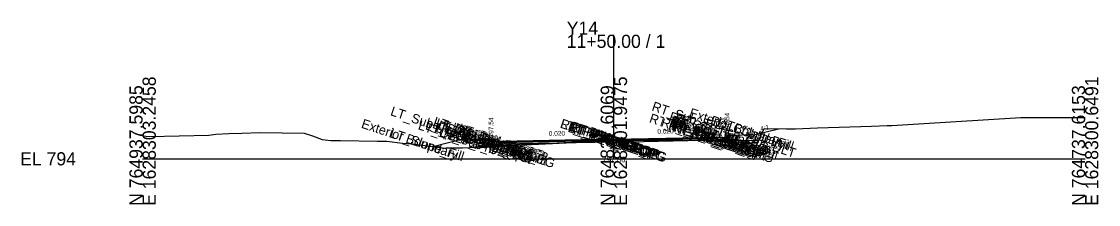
# Model space of a CAD drawing. Extents: x -26 to 1403, y -10 to 4517.
# Drawn here: x -25.7 to 202.8, y 2990.3 to 3029.1 of the extents above; entities that cross this region are included whole.
import ezdxf

# ---------------------------------------------------------------- set-up
doc = ezdxf.new("R2010")
doc.units = 0
for name, color, linetype in [('Default', 7, 'Continuous'), ('Exist CMT Pavement', 7, 'Continuous'), ('Exist Cross Section Cell', 7, 'Continuous'), ('Exist XS Center Line Elevation Label', 7, 'Continuous'), ('Exist XS Ground Line', 7, 'Continuous'), ('Prop CMT Conc Surface', 7, 'Continuous'), ('Prop CMT Concrete Structures', 7, 'Continuous'), ('Prop CMT Pvmt Course 1', 7, 'Continuous'), ('Prop CMT Pvmt Course 1 CG', 7, 'Continuous'), ('Prop CMT Pvmt Course 1 Wedge', 7, 'Continuous'), ('Prop CMT Pvmt Course 2', 7, 'Continuous'), ('Prop CMT Pvmt Course 2 Wedge', 7, 'Continuous'), ('Prop CMT Pvmt Course 3', 7, 'Continuous'), ('Prop CMT Pvmt Course 3 Wedge', 7, 'Continuous'), ('Prop CMT Pvmt Surface', 7, 'Continuous'), ('Prop CMT Pvmt Wedge Surface 1', 7, 'Continuous'), ('Prop CMT Pvmt Wedge Surface 2', 7, 'Continuous'), ('Prop CMT Pvmt Wedge Surface 3', 7, 'Continuous'), ('Prop CMT Slope Grass', 7, 'Continuous'), ('Prop CMT Subgrade Earthwork', 7, 'Continuous'), ('Prop XS Hydro Elevations', 7, 'Continuous'), ('Prop XS SE Text', 7, 'Continuous'), ('Prop XS Side Slope Text', 7, 'Continuous'), ('Scratch_Level_0', 7, 'Continuous')]:
    doc.layers.add(name, color=color, linetype=linetype)

msp = doc.modelspace()

# ---------------------------------------------------------------- linework, layer by layer
at = {"layer": 'Exist CMT Pavement'}
for points in [[(100, 3003.86), (97.67, 3003.84), (91.36, 3003.45), (75.94, 3002.73)], [(100, 3003.86), (75.94, 3002.77)], [(100, 3003.86), (101.84, 3003.87), (122.02, 3003.95)], [(100, 3003.86), (122.02, 3003.95)]]:
    msp.add_lwpolyline(points, dxfattribs=at)
at = {"layer": 'Exist Cross Section Cell'}
for p, q in [((100, 3000), (100, 3026.34)), ((0, 3000), (100, 3000)), ((100, 3000), (200, 3000))]:
    msp.add_line(p, q, dxfattribs=at)
at = {"layer": 'Exist XS Ground Line'}
msp.add_lwpolyline([(0, 3004.91), (1.48, 3004.77), (14.07, 3004.99), (15.54, 3005.21), (18.3, 3005.39), (21.03, 3005.45), (24.94, 3005.57), (34.29, 3005.43), (36.02, 3004.91), (38.09, 3004.1), (39.91, 3003.88), (41.98, 3003.88), (49.84, 3003.77), (51.83, 3003.75), (55.16, 3003.29), (56.97, 3003.15), (60.47, 3002.72), (64.12, 3002.23), (64.4, 3002.35), (67.85, 3002.36), (91.36, 3003.45), (97.67, 3003.84), (100, 3003.86), (101.84, 3003.87), (130.78, 3003.98), (131, 3004.01), (131.11, 3004.71), (131.91, 3006.41), (136.62, 3006.36), (137.32, 3006.35), (138.55, 3006.37), (143.22, 3006.54), (154.71, 3006.92), (158, 3007.08), (158.97, 3007.07), (164.65, 3007.41), (186.36, 3008.76), (200, 3008.78)], dxfattribs=at)
at = {"layer": 'Prop CMT Conc Surface'}
for points in [[(73.94, 3003.54), (73.94, 3004.04), (73.44, 3004.04)], [(75.94, 3003.66), (73.94, 3003.54)], [(122.02, 3004.58), (124.02, 3004.54)], [(124.02, 3004.54), (124.02, 3005.04), (124.52, 3005.04)]]:
    msp.add_lwpolyline(points, dxfattribs=at)
at = {"layer": 'Prop CMT Concrete Structures'}
for points in [[(75.94, 3003.66), (73.94, 3003.54), (73.94, 3004.04), (73.44, 3004.04)], [(73.44, 3004.04), (73.44, 3003.03), (75.94, 3003.08)], [(75.94, 3003.08), (75.94, 3003.66)], [(122.02, 3004.58), (124.02, 3004.54), (124.02, 3005.04), (124.52, 3005.04)], [(124.52, 3005.04), (124.52, 3004.05), (122.02, 3004)], [(122.02, 3004), (122.02, 3004.58)]]:
    msp.add_lwpolyline(points, dxfattribs=at)
at = {"layer": 'Prop CMT Pvmt Course 1'}
for points in [[(100, 3004.14), (75.94, 3003.66)], [(75.94, 3003.53), (100, 3004.02)], [(75.94, 3003.66), (75.94, 3003.41), (75.94, 3003.41), (75.94, 3003.53)], [(100, 3004.14), (122.02, 3004.58)], [(122.02, 3004.46), (100, 3004.02)], [(100, 3003.89), (100, 3004.14)], [(100, 3003.89), (100, 3004.14)], [(100, 3004.02), (100, 3003.89), (100, 3003.89)], [(100, 3004.02), (100, 3003.89), (100, 3003.89)], [(122.02, 3004.58), (122.02, 3004.33), (122.02, 3004.33), (122.02, 3004.46)]]:
    msp.add_lwpolyline(points, dxfattribs=at)
at = {"layer": 'Prop CMT Pvmt Course 1 CG'}
for points in [[(75.94, 3003.08), (72.94, 3003.02), (72.6, 3002.68)], [(75.94, 3002.74), (75.94, 3003.08)], [(122.02, 3004), (125.02, 3004.06), (125.34, 3003.73)], [(122.02, 3003.66), (122.02, 3004)], [(125.34, 3003.73), (122.02, 3003.66)], [(72.6, 3002.68), (75.94, 3002.74)]]:
    msp.add_lwpolyline(points, dxfattribs=at)
at = {"layer": 'Prop CMT Pvmt Course 1 Wedge'}
for points in [[(100, 3004.02), (75.94, 3003.53)], [(100, 3004.02), (122.02, 3004.46)]]:
    msp.add_lwpolyline(points, dxfattribs=at)
at = {"layer": 'Prop CMT Pvmt Course 2'}
for points in [[(75.94, 3003.08), (75.94, 3003.08), (75.94, 3003.41), (75.94, 3003.41)], [(75.94, 3003.41), (75.94, 3003.08)], [(122.02, 3004), (122.02, 3004), (122.02, 3004.33), (122.02, 3004.33)], [(122.02, 3004.33), (122.02, 3004)]]:
    msp.add_lwpolyline(points, dxfattribs=at)
at = {"layer": 'Prop CMT Pvmt Course 2 Wedge'}
for points in [[(100, 3003.89), (75.94, 3003.41)], [(100, 3003.89), (122.02, 3004.33)]]:
    msp.add_lwpolyline(points, dxfattribs=at)
at = {"layer": 'Prop CMT Pvmt Course 3'}
for points in [[(75.94, 3003.08), (75.94, 3003.08), (75.94, 3002.74), (75.94, 3002.74)], [(75.94, 3002.74), (75.94, 3003.08)], [(122.02, 3004), (122.02, 3004), (122.02, 3003.66), (122.02, 3003.66)], [(122.02, 3003.66), (122.02, 3004)]]:
    msp.add_lwpolyline(points, dxfattribs=at)
at = {"layer": 'Prop CMT Pvmt Course 3 Wedge'}
for points in [[(100, 3003.56), (75.94, 3003.08)], [(100, 3003.56), (122.02, 3004)]]:
    msp.add_lwpolyline(points, dxfattribs=at)
at = {"layer": 'Prop CMT Pvmt Surface'}
for points in [[(100, 3004.14), (75.94, 3003.66)], [(100, 3004.14), (122.02, 3004.58)]]:
    msp.add_lwpolyline(points, dxfattribs=at)
at = {"layer": 'Prop CMT Pvmt Wedge Surface 1'}
for points in [[(100, 3004.02), (75.94, 3003.53)], [(75.94, 3003.41), (75.94, 3003.66)], [(75.94, 3003.53), (75.94, 3003.41), (75.94, 3003.41)], [(100, 3004.02), (122.02, 3004.46)], [(122.02, 3004.33), (122.02, 3004.58)], [(122.02, 3004.46), (122.02, 3004.33), (122.02, 3004.33)]]:
    msp.add_lwpolyline(points, dxfattribs=at)
at = {"layer": 'Prop CMT Pvmt Wedge Surface 2'}
for points in [[(100, 3003.89), (75.94, 3003.41)], [(75.94, 3003.41), (75.94, 3003.66)], [(100, 3003.89), (122.02, 3004.33)], [(122.02, 3004.33), (122.02, 3004.58)]]:
    msp.add_lwpolyline(points, dxfattribs=at)
at = {"layer": 'Prop CMT Pvmt Wedge Surface 3'}
for points in [[(75.94, 3003.08), (75.94, 3003.66)], [(100, 3003.56), (75.94, 3003.08)], [(100, 3003.56), (122.02, 3004)], [(122.02, 3004), (122.02, 3004.58)]]:
    msp.add_lwpolyline(points, dxfattribs=at)
at = {"layer": 'Prop CMT Slope Grass'}
for points in [[(124.52, 3005.04), (130.02, 3005.15), (134.94, 3006.38)], [(73.44, 3004.04), (67.94, 3004.15), (61.61, 3002.57)]]:
    msp.add_lwpolyline(points, dxfattribs=at)
at = {"layer": 'Prop CMT Subgrade Earthwork'}
for points in [[(75.94, 3002.74), (72.6, 3002.68), (71.19, 3004.08)], [(122.02, 3003.66), (122, 3003.95)], [(122.02, 3003.66), (125.34, 3003.73), (126.7, 3005.08)], [(122.02, 3003.66), (122.02, 3003.66)], [(75.94, 3002.74), (75.96, 3002.77)], [(75.94, 3002.74), (75.94, 3002.74)]]:
    msp.add_lwpolyline(points, dxfattribs=at)

# ---------------------------------------------------------------- texts
at = {"layer": 'Default'}
msp.add_text('-', height=0.0001, dxfattribs=at).set_placement((0, 3000))
at = {"layer": 'Exist Cross Section Cell'}
for s, p in [('Y14', (90, 3026.34)), ('11+50.00 / 1', (90, 3023.54)), ('EL 794', (-26, 2998.6))]:
    msp.add_text(s, height=2.8, dxfattribs=at).set_placement(p)
for s, p in [('E 1628303.2458', (2.8, 2990)), ('E 1628301.9475', (102.8, 2990)), ('E 1628300.6491', (202.8, 2990)), ('N 764937.5985', (0, 2990)), ('N 764837.6069', (100, 2990)), ('N 764737.6153', (200, 2990))]:
    msp.add_text(s, height=2.8, rotation=90, dxfattribs=at).set_placement(p)
at = {"layer": 'Exist XS Center Line Elevation Label'}
msp.add_text('797.86', height=1.2, dxfattribs=at).set_placement((97.54, 2999.26))
at = {"layer": 'Prop XS Hydro Elevations'}
for s, p in [('797.54', (74.44, 3004.54)), ('798.54', (124.52, 3005.54))]:
    msp.add_text(s, height=1, rotation=90, dxfattribs=at).set_placement(p)
at = {"layer": 'Prop XS SE Text'}
for p in [(86.2, 3004.86), (109.24, 3005.33)]:
    msp.add_text('0.020', height=1, rotation=1.1458, dxfattribs=at).set_placement(p)
at = {"layer": 'Prop XS Side Slope Text'}
for p in [(63.82, 3003.89), (131.2, 3005.83)]:
    msp.add_text('4:1', height=1, rotation=14.0362, dxfattribs=at).set_placement(p)
at = {"layer": 'Scratch_Level_0'}
for s, p in [('RT_Sub_Trench_Out_DLT', (107.9, 3010.3)), ('LT_Sub_Trench_Out_DLT', (52.44, 3009.28)), ('RT_CG_Top_Face', (111.57, 3008.14)), ('Exterior Boundary', (115.82, 3008.93)), ('Exterior Boundary', (46.25, 3006.63)), ('LT_CSLP_Pnt', (58.3, 3006.31)), ('LT_CG1_Shelf_Out', (59.87, 3006.32)), ('LT_PV_Sub_Tie_Out', (61.36, 3006.59)), ('LT_CG_Top_Face', (61.54, 3007.12)), ('LT_CG_Top_BOC', (62.01, 3006.8)), ('LT_CG_Bot_BOC', (62.04, 3005.77)), ('LT_CG_Top_Gut', (62.47, 3006.31)), ('LT_PV_OEEOP_EG', (63.81, 3005.76)), ('LT_PV2_OEEOP', (65.48, 3005.84)), ('LT_PV1_OEEOP', (66.02, 3005.79)), ('RT_PV_IEEOP_EG', (88.43, 3006.66)), ('LT_PV_IEEOP_EG', (88.48, 3006.65)), ('RT_PV2_IEEOP', (90.11, 3006.13)), ('RT_PV3_IEEOP', (90.11, 3005.8)), ('LT_PV2_IEEOP', (90.15, 3006.12)), ('LT_PV3_IEEOP', (90.15, 3005.79)), ('RT_PV1_IEEOP', (90.65, 3006.08)), ('LT_PV1_IEEOP', (90.69, 3006.06)), ('RT_PV_Sub_Tie_Out', (107.36, 3007.78)), ('RT_PV_OEEOP_EG', (109.84, 3006.95)), ('RT_Sub_OEEOP', (111.42, 3006.14)), ('RT_PV2_OEEOP', (111.51, 3006.78)), ('RT_PV3_OEEOP', (111.51, 3006.45)), ('RT_CG1_Shelf_Out', (111.9, 3007.38)), ('RT_PV1_OEEOP', (112.05, 3006.72)), ('RT_CG_Bot_IE', (112.09, 3006.25)), ('RT_Sub_OEOT', (112.24, 3005.87)), ('RT_PV2_OEOT', (112.33, 3006.5)), ('RT_PV3_OEOT', (112.33, 3006.17)), ('RT_CG_Top_Gut', (112.5, 3007.33)), ('RT_PV1_OEOT', (112.87, 3006.58)), ('RT_CG_Top_BOC', (113.04, 3007.81)), ('RT_CG_Bot_BOC', (113.07, 3006.81)), ('RT_Sub_OEOP', (115.6, 3005.92)), ('RT_CSLP_Pnt', (120.33, 3007.32)), ('RT_Slope_Fill', (121.83, 3006.92)), ('LT_Slope_Fill', (52.3, 3004.62)), ('LT_Sub_OEOP', (62.9, 3004.85)), ('LT_Sub_OEEOP', (65.39, 3005.21)), ('LT_PV3_OEEOP', (65.48, 3005.51)), ('LT_CG_Bot_IE', (66.06, 3005.32)), ('LT_Sub_OEOT', (66.21, 3004.93)), ('LT_PV2_OEOT', (66.3, 3005.57)), ('LT_PV3_OEOT', (66.3, 3005.23)), ('LT_PV1_OEOT', (66.84, 3005.64)), ('PV2_PGL', (93.9, 3004.87)), ('PV1_PGL', (94.44, 3004.94))]:
    msp.add_text(s, height=2, rotation=341.5651, dxfattribs=at).set_placement(p)

doc.saveas('drawing.dxf')
